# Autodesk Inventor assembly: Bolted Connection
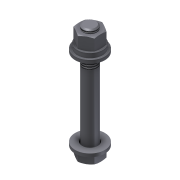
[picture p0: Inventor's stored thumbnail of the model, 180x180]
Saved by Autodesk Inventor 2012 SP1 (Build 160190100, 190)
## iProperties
Created: 2006-03
Part Number: Bolted Connection
Document SubType Name: Assembly
Designer: Administrator
ClientObjectVersion: 1
Author: Administrator
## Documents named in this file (5)
- D:\AOTC\Autodesk Inventor 2012 Essential for New Users\Autodesk Inventor 2012 Essentials - Project Files\Learning\Workspace\Sub-Assemblies\Design Accelerator\Bolted Connection2.iam
- D:\AOTC\Autodesk Inventor 2012 Essential for New Users\Autodesk Inventor 2012 Essentials - Project Files\Learning\Workspace\Libraries\Content Center Files\en-US\Plain Washer (Metric)\12-25.4.ipt
- D:\AOTC\Autodesk Inventor 2012 Essential for New Users\Autodesk Inventor 2012 Essentials - Project Files\Learning\Workspace\Libraries\Content Center Files\en-US\AS 1111  - Metric\M12-90.ipt
- D:\AOTC\Autodesk Inventor 2012 Essential for New Users\Autodesk Inventor 2012 Essentials - Project Files\Learning\Workspace\Libraries\Content Center Files\en-US\Hex Nut Metric\M12-Style 1.ipt
- D:\AOTC\Autodesk Inventor 2012 Essential for New Users\Autodesk Inventor 2012 Essentials - Project Files\Learning\Workspace\Libraries\Content Center Files\en-US\ASME B18.21.2M\12.ipt
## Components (5 placed, 4 different names)
1. Plain Washer (Metric) 12 N:1
2. AS 1111  - Metric M12 x 90:1
3. Plain Washer (Metric) 12 N:2
4. ASME B18.21.2M 12:1
5. Hex Nut Metric M12 x 1.75:1
